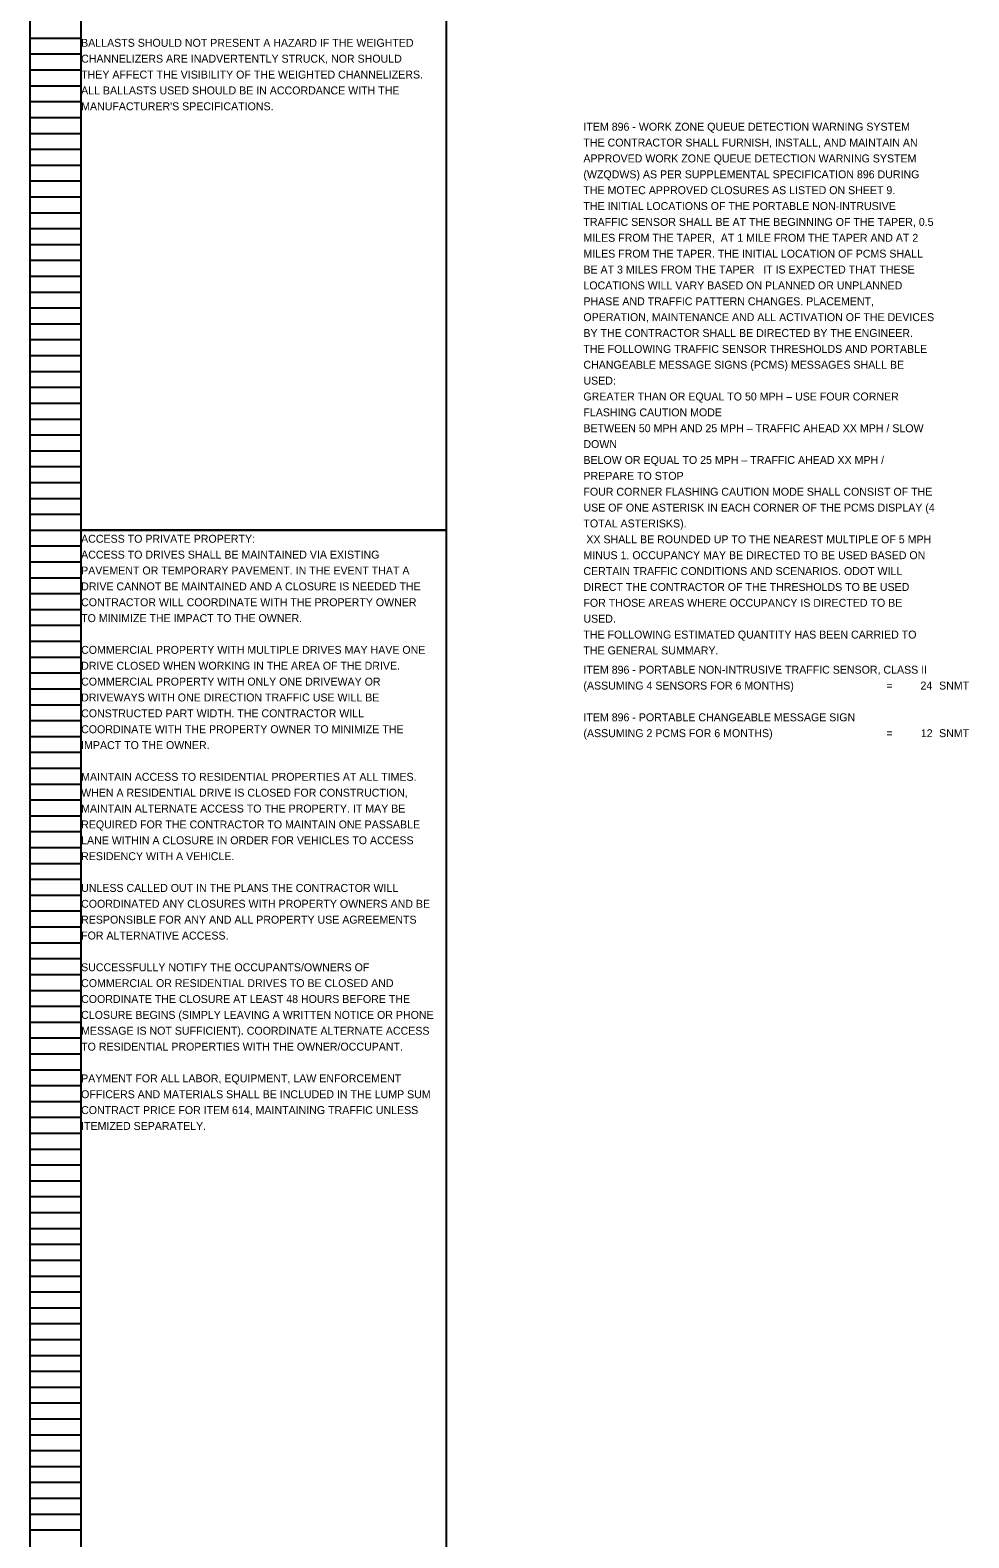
# Model space of a CAD drawing. Extents: x 16463 to 16500, y 5400 to 5823.
# Drawn here: x 16463.05 to 16479.61, y 5664.57 to 5691.17 of the extents above; entities that cross this region are included whole.
import ezdxf

# ---------------------------------------------------------------- set-up
doc = ezdxf.new("R2010")
doc.units = 0
for name, color, linetype in [('Default', 7, 'Continuous'), ('SC_Scratch1', 7, 'Continuous'), ('SH_Data', 7, 'Continuous')]:
    doc.layers.add(name, color=color, linetype=linetype)

msp = doc.modelspace()

# ---------------------------------------------------------------- linework, layer by layer
at = {"layer": 'SC_Scratch1'}
for points in [[(16463.949, 5702.512), (16470.389, 5702.512), (16470.389, 5682.352), (16463.949, 5682.352)], [(16463.949, 5682.352), (16470.389, 5682.352), (16470.389, 5662.192), (16463.949, 5662.192)]]:
    msp.add_lwpolyline(points, close=True, dxfattribs=at)
at = {"layer": 'SH_Data'}
for p, q in [((16463.049, 5682.352), (16463.049, 5702.512)), ((16463.949, 5682.352), (16463.949, 5702.512)), ((16463.049, 5691.032), (16463.949, 5691.032)), ((16463.049, 5690.752), (16463.949, 5690.752)), ((16463.049, 5690.472), (16463.949, 5690.472)), ((16463.049, 5690.192), (16463.949, 5690.192)), ((16463.049, 5689.912), (16463.949, 5689.912)), ((16463.049, 5689.632), (16463.949, 5689.632)), ((16463.049, 5689.352), (16463.949, 5689.352)), ((16463.049, 5689.072), (16463.949, 5689.072)), ((16463.049, 5688.792), (16463.949, 5688.792)), ((16463.049, 5688.512), (16463.949, 5688.512)), ((16463.049, 5688.232), (16463.949, 5688.232)), ((16463.049, 5687.952), (16463.949, 5687.952)), ((16463.049, 5687.672), (16463.949, 5687.672)), ((16463.049, 5687.392), (16463.949, 5687.392)), ((16463.049, 5687.112), (16463.949, 5687.112)), ((16463.049, 5686.832), (16463.949, 5686.832)), ((16463.049, 5686.552), (16463.949, 5686.552)), ((16463.049, 5686.272), (16463.949, 5686.272)), ((16463.049, 5685.992), (16463.949, 5685.992)), ((16463.049, 5685.712), (16463.949, 5685.712)), ((16463.049, 5685.432), (16463.949, 5685.432)), ((16463.049, 5685.152), (16463.949, 5685.152)), ((16463.049, 5684.872), (16463.949, 5684.872)), ((16463.049, 5684.592), (16463.949, 5684.592)), ((16463.049, 5684.312), (16463.949, 5684.312)), ((16463.049, 5684.032), (16463.949, 5684.032)), ((16463.049, 5683.752), (16463.949, 5683.752)), ((16463.049, 5683.472), (16463.949, 5683.472)), ((16463.049, 5683.192), (16463.949, 5683.192)), ((16463.049, 5682.912), (16463.949, 5682.912)), ((16463.049, 5682.632), (16463.949, 5682.632)), ((16463.049, 5662.192), (16463.049, 5682.352)), ((16463.049, 5682.352), (16463.949, 5682.352)), ((16463.049, 5682.352), (16463.949, 5682.352)), ((16463.949, 5662.192), (16463.949, 5682.352)), ((16463.049, 5682.072), (16463.949, 5682.072)), ((16463.049, 5681.792), (16463.949, 5681.792)), ((16463.049, 5681.512), (16463.949, 5681.512)), ((16463.049, 5681.232), (16463.949, 5681.232)), ((16463.049, 5680.952), (16463.949, 5680.952)), ((16463.049, 5680.672), (16463.949, 5680.672)), ((16463.049, 5680.392), (16463.949, 5680.392)), ((16463.049, 5680.112), (16463.949, 5680.112)), ((16463.049, 5679.832), (16463.949, 5679.832)), ((16463.049, 5679.552), (16463.949, 5679.552)), ((16463.049, 5679.272), (16463.949, 5679.272)), ((16463.049, 5678.992), (16463.949, 5678.992)), ((16463.049, 5678.712), (16463.949, 5678.712)), ((16463.049, 5678.432), (16463.949, 5678.432)), ((16463.049, 5678.152), (16463.949, 5678.152)), ((16463.049, 5677.872), (16463.949, 5677.872)), ((16463.049, 5677.592), (16463.949, 5677.592)), ((16463.049, 5677.312), (16463.949, 5677.312)), ((16463.049, 5677.032), (16463.949, 5677.032)), ((16463.049, 5676.752), (16463.949, 5676.752)), ((16463.049, 5676.472), (16463.949, 5676.472)), ((16463.049, 5676.192), (16463.949, 5676.192)), ((16463.049, 5675.912), (16463.949, 5675.912)), ((16463.049, 5675.632), (16463.949, 5675.632)), ((16463.049, 5675.352), (16463.949, 5675.352)), ((16463.049, 5675.072), (16463.949, 5675.072)), ((16463.049, 5674.792), (16463.949, 5674.792)), ((16463.049, 5674.512), (16463.949, 5674.512)), ((16463.049, 5674.232), (16463.949, 5674.232)), ((16463.049, 5673.952), (16463.949, 5673.952)), ((16463.049, 5673.672), (16463.949, 5673.672)), ((16463.049, 5673.392), (16463.949, 5673.392)), ((16463.049, 5673.112), (16463.949, 5673.112)), ((16463.049, 5672.832), (16463.949, 5672.832)), ((16463.049, 5672.552), (16463.949, 5672.552)), ((16463.049, 5672.272), (16463.949, 5672.272)), ((16463.049, 5671.992), (16463.949, 5671.992)), ((16463.049, 5671.712), (16463.949, 5671.712)), ((16463.049, 5671.432), (16463.949, 5671.432)), ((16463.049, 5671.152), (16463.949, 5671.152)), ((16463.049, 5670.872), (16463.949, 5670.872)), ((16463.049, 5670.592), (16463.949, 5670.592)), ((16463.049, 5670.312), (16463.949, 5670.312)), ((16463.049, 5670.032), (16463.949, 5670.032)), ((16463.049, 5669.752), (16463.949, 5669.752)), ((16463.049, 5669.472), (16463.949, 5669.472)), ((16463.049, 5669.192), (16463.949, 5669.192)), ((16463.049, 5668.912), (16463.949, 5668.912)), ((16463.049, 5668.632), (16463.949, 5668.632)), ((16463.049, 5668.352), (16463.949, 5668.352)), ((16463.049, 5668.072), (16463.949, 5668.072)), ((16463.049, 5667.792), (16463.949, 5667.792)), ((16463.049, 5667.512), (16463.949, 5667.512)), ((16463.049, 5667.232), (16463.949, 5667.232)), ((16463.049, 5666.952), (16463.949, 5666.952)), ((16463.049, 5666.672), (16463.949, 5666.672)), ((16463.049, 5666.392), (16463.949, 5666.392)), ((16463.049, 5666.112), (16463.949, 5666.112)), ((16463.049, 5665.832), (16463.949, 5665.832)), ((16463.049, 5665.552), (16463.949, 5665.552)), ((16463.049, 5665.272), (16463.949, 5665.272)), ((16463.049, 5664.992), (16463.949, 5664.992)), ((16463.049, 5664.712), (16463.949, 5664.712))]:
    msp.add_line(p, q, dxfattribs=at)

# ---------------------------------------------------------------- texts
at = {"layer": 'Default'}
for s, p in [('BALLASTS SHOULD NOT PRESENT A HAZARD IF THE WEIGHTED ', (16463.949, 5690.879)), ('CHANNELIZERS ARE INADVERTENTLY STRUCK, NOR SHOULD ', (16463.949, 5690.599)), ('THEY AFFECT THE VISIBILITY OF THE WEIGHTED CHANNELIZERS.  ', (16463.949, 5690.319)), ('ALL BALLASTS USED SHOULD BE IN ACCORDANCE WITH THE ', (16463.949, 5690.039)), ("MANUFACTURER'S SPECIFICATIONS.", (16463.949, 5689.759)), ('ITEM 896 - WORK ZONE QUEUE DETECTION WARNING SYSTEM ', (16472.813, 5689.399)), ('THE CONTRACTOR SHALL FURNISH, INSTALL, AND MAINTAIN AN ', (16472.813, 5689.119)), ('APPROVED WORK ZONE QUEUE DETECTION WARNING SYSTEM ', (16472.813, 5688.839)), ('(WZQDWS) AS PER SUPPLEMENTAL SPECIFICATION 896 DURING ', (16472.813, 5688.559)), ('THE MOTEC APPROVED CLOSURES AS LISTED ON SHEET 9.', (16472.813, 5688.279)), ('THE INITIAL LOCATIONS OF THE PORTABLE NON-INTRUSIVE ', (16472.813, 5687.999)), ('TRAFFIC SENSOR SHALL BE AT THE BEGINNING OF THE TAPER, 0.5 ', (16472.813, 5687.719)), ('MILES FROM THE TAPER,  AT 1 MILE FROM THE TAPER AND AT 2 ', (16472.813, 5687.439)), ('MILES FROM THE TAPER. THE INITIAL LOCATION OF PCMS SHALL ', (16472.813, 5687.159)), ('BE AT 3 MILES FROM THE TAPER   IT IS EXPECTED THAT THESE ', (16472.813, 5686.879)), ('LOCATIONS WILL VARY BASED ON PLANNED OR UNPLANNED ', (16472.813, 5686.599)), ('PHASE AND TRAFFIC PATTERN CHANGES. PLACEMENT, ', (16472.813, 5686.319)), ('OPERATION, MAINTENANCE AND ALL ACTIVATION OF THE DEVICES ', (16472.813, 5686.039)), ('BY THE CONTRACTOR SHALL BE DIRECTED BY THE ENGINEER.', (16472.813, 5685.759)), ('THE FOLLOWING TRAFFIC SENSOR THRESHOLDS AND PORTABLE ', (16472.813, 5685.479)), ('CHANGEABLE MESSAGE SIGNS (PCMS) MESSAGES SHALL BE ', (16472.813, 5685.199)), ('USED:', (16472.813, 5684.919)), ('GREATER THAN OR EQUAL TO 50 MPH – USE FOUR CORNER ', (16472.813, 5684.639)), ('FLASHING CAUTION MODE ', (16472.813, 5684.359)), ('BETWEEN 50 MPH AND 25 MPH – TRAFFIC AHEAD XX MPH / SLOW ', (16472.813, 5684.079)), ('DOWN ', (16472.813, 5683.799)), ('BELOW OR EQUAL TO 25 MPH – TRAFFIC AHEAD XX MPH / ', (16472.813, 5683.519)), ('PREPARE TO STOP ', (16472.813, 5683.239)), ('FOUR CORNER FLASHING CAUTION MODE SHALL CONSIST OF THE ', (16472.813, 5682.959)), ('USE OF ONE ASTERISK IN EACH CORNER OF THE PCMS DISPLAY (4 ', (16472.813, 5682.679)), ('TOTAL ASTERISKS).', (16472.813, 5682.399)), ('ACCESS TO PRIVATE PROPERTY:', (16463.949, 5682.129)), (' XX SHALL BE ROUNDED UP TO THE NEAREST MULTIPLE OF 5 MPH ', (16472.813, 5682.119)), ('ACCESS TO DRIVES SHALL BE MAINTAINED VIA EXISTING ', (16463.949, 5681.849)), ('MINUS 1. OCCUPANCY MAY BE DIRECTED TO BE USED BASED ON ', (16472.813, 5681.839)), ('PAVEMENT OR TEMPORARY PAVEMENT. IN THE EVENT THAT A ', (16463.949, 5681.569)), ('CERTAIN TRAFFIC CONDITIONS AND SCENARIOS. ODOT WILL ', (16472.813, 5681.559)), ('DRIVE CANNOT BE MAINTAINED AND A CLOSURE IS NEEDED THE ', (16463.949, 5681.289)), ('DIRECT THE CONTRACTOR OF THE THRESHOLDS TO BE USED ', (16472.813, 5681.279)), ('CONTRACTOR WILL COORDINATE WITH THE PROPERTY OWNER ', (16463.949, 5681.009)), ('FOR THOSE AREAS WHERE OCCUPANCY IS DIRECTED TO BE ', (16472.813, 5680.999)), ('TO MINIMIZE THE IMPACT TO THE OWNER.', (16463.949, 5680.729)), ('USED. ', (16472.813, 5680.719)), ('THE FOLLOWING ESTIMATED QUANTITY HAS BEEN CARRIED TO ', (16472.813, 5680.439)), ('COMMERCIAL PROPERTY WITH MULTIPLE DRIVES MAY HAVE ONE ', (16463.949, 5680.169)), ('THE GENERAL SUMMARY.', (16472.813, 5680.159)), ('DRIVE CLOSED WHEN WORKING IN THE AREA OF THE DRIVE. ', (16463.949, 5679.889)), ('COMMERCIAL PROPERTY WITH ONLY ONE DRIVEWAY OR ', (16463.949, 5679.609)), ('DRIVEWAYS WITH ONE DIRECTION TRAFFIC USE WILL BE ', (16463.949, 5679.329)), ('CONSTRUCTED PART WIDTH. THE CONTRACTOR WILL ', (16463.949, 5679.049)), ('COORDINATE WITH THE PROPERTY OWNER TO MINIMIZE THE ', (16463.949, 5678.769)), ('IMPACT TO THE OWNER.', (16463.949, 5678.489)), ('MAINTAIN ACCESS TO RESIDENTIAL PROPERTIES AT ALL TIMES. ', (16463.949, 5677.929)), ('WHEN A RESIDENTIAL DRIVE IS CLOSED FOR CONSTRUCTION, ', (16463.949, 5677.649)), ('MAINTAIN ALTERNATE ACCESS TO THE PROPERTY. IT MAY BE ', (16463.949, 5677.369)), ('REQUIRED FOR THE CONTRACTOR TO MAINTAIN ONE PASSABLE ', (16463.949, 5677.089)), ('LANE WITHIN A CLOSURE IN ORDER FOR VEHICLES TO ACCESS ', (16463.949, 5676.809)), ('RESIDENCY WITH A VEHICLE.', (16463.949, 5676.529)), ('UNLESS CALLED OUT IN THE PLANS THE CONTRACTOR WILL ', (16463.949, 5675.969)), ('COORDINATED ANY CLOSURES WITH PROPERTY OWNERS AND BE ', (16463.949, 5675.689)), ('RESPONSIBLE FOR ANY AND ALL PROPERTY USE AGREEMENTS ', (16463.949, 5675.409)), ('FOR ALTERNATIVE ACCESS.', (16463.949, 5675.129)), ('SUCCESSFULLY NOTIFY THE OCCUPANTS/OWNERS OF ', (16463.949, 5674.569)), ('COMMERCIAL OR RESIDENTIAL DRIVES TO BE CLOSED AND ', (16463.949, 5674.289)), ('COORDINATE THE CLOSURE AT LEAST 48 HOURS BEFORE THE ', (16463.949, 5674.009)), ('CLOSURE BEGINS (SIMPLY LEAVING A WRITTEN NOTICE OR PHONE ', (16463.949, 5673.729)), ('MESSAGE IS NOT SUFFICIENT). COORDINATE ALTERNATE ACCESS ', (16463.949, 5673.449)), ('TO RESIDENTIAL PROPERTIES WITH THE OWNER/OCCUPANT.', (16463.949, 5673.169)), ('PAYMENT FOR ALL LABOR, EQUIPMENT, LAW ENFORCEMENT ', (16463.949, 5672.609)), ('OFFICERS AND MATERIALS SHALL BE INCLUDED IN THE LUMP SUM ', (16463.949, 5672.329)), ('CONTRACT PRICE FOR ITEM 614, MAINTAINING TRAFFIC UNLESS ', (16463.949, 5672.049)), ('ITEMIZED SEPARATELY.', (16463.949, 5671.769))]:
    msp.add_text(s, height=0.14, dxfattribs=at).set_placement(p)
at = {"layer": 'SC_Scratch1'}
for s, p in [('ITEM 896 - PORTABLE NON-INTRUSIVE TRAFFIC SENSOR, CLASS II', (16472.813, 5679.819)), ('(ASSUMING 4 SENSORS FOR 6 MONTHS)', (16472.813, 5679.539)), (' =', (16478.107, 5679.539)), ('24', (16478.761, 5679.539)), ('SNMT', (16479.089, 5679.539)), ('ITEM 896 - PORTABLE CHANGEABLE MESSAGE SIGN', (16472.813, 5678.979)), ('(ASSUMING 2 PCMS FOR 6 MONTHS)', (16472.813, 5678.699)), ('12', (16478.767, 5678.699)), ('SNMT', (16479.089, 5678.699)), (' =', (16478.107, 5678.699))]:
    msp.add_text(s, height=0.14, dxfattribs=at).set_placement(p)

doc.saveas('drawing.dxf')
